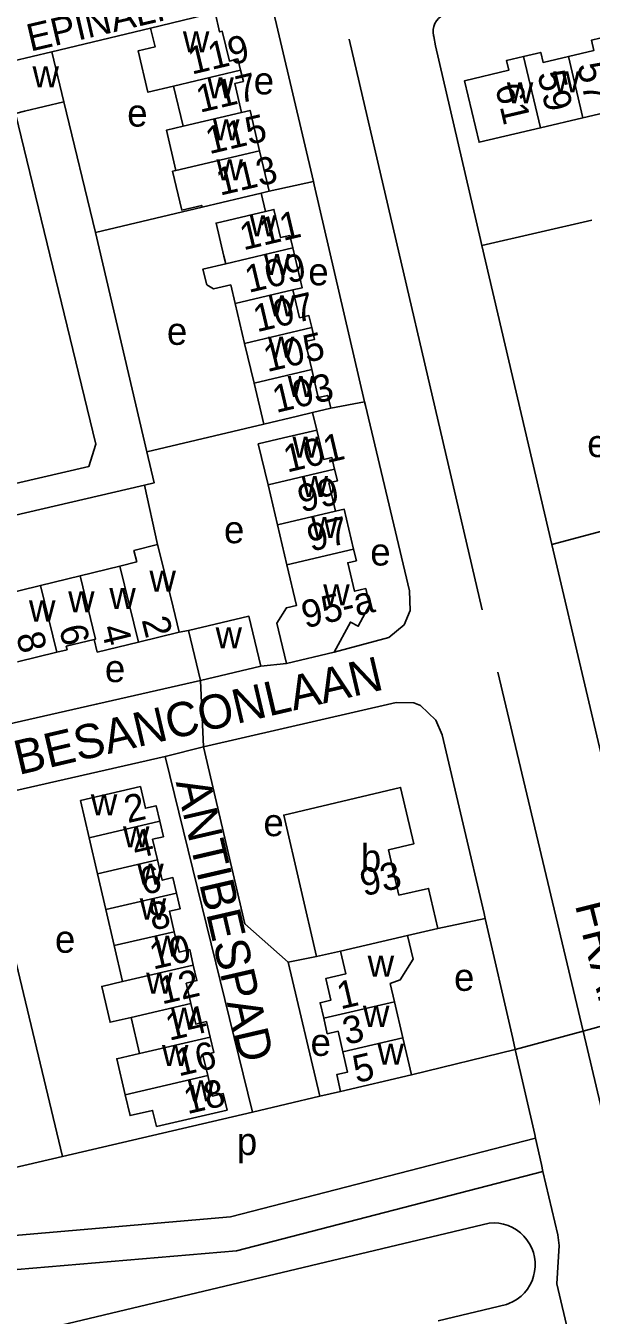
# Model space of a CAD drawing. Extents: x 157768 to 159790, y 387230 to 389604.
# Drawn here: x 159272.3 to 159355, y 388292.4 to 388480.9 of the extents above; entities that cross this region are included whole.
import ezdxf

# ---------------------------------------------------------------- set-up
doc = ezdxf.new("R2010")
doc.units = 0
for name, color, linetype in [('BLT_Basislijn', 7, 'Continuous'), ('BLT_Bebouwing', 7, 'Continuous'), ('BLT_Centroide', 7, 'Continuous'), ('BLT_Huisnummer', 7, 'Continuous'), ('BLT_Huisnummer_ tussenligend', 7, 'Continuous'), ('BLT_Huisnummer_reeks', 7, 'Continuous'), ('BLT_Onderverdeling_panden', 7, 'Continuous'), ('BLT_Straatnaam', 7, 'Continuous'), ('BLT_Straatnaam_verkleind', 7, 'Continuous'), ('BLT_Vlakafsluiter', 7, 'Continuous')]:
    doc.layers.add(name, color=color, linetype=linetype)

msp = doc.modelspace()

# ---------------------------------------------------------------- linework, layer by layer
at = {"layer": 'BLT_Basislijn'}
for p, q in [((159314.37, 388458.12), (159308.15, 388484.57)), ((159276.16, 388477.1), (159290.58, 388480.53)), ((159319.59, 388478.93), (159339.01, 388395.52)), ((159332.23, 388477.95), (159331.97, 388479.3)), ((159282.52, 388450.68), (159277.89, 388469.76)), ((159307.9, 388456.71), (159314.37, 388458.12)), ((159306.74, 388456.43), (159307.36, 388453.76)), ((159298.12, 388454.39), (159282.52, 388450.68)), ((159355.07, 388452.48), (159338.98, 388448.78)), ((159290.03, 388418.62), (159282.52, 388450.68)), ((159349.2, 388405.07), (159338.98, 388448.78)), ((159316.91, 388424.97), (159321.83, 388425.93)), ((159314.25, 388424.34), (159314.87, 388421.8)), ((159307.11, 388422.65), (159290.03, 388418.62)), ((159289.69, 388413.74), (159254.44, 388405.52)), ((159289.69, 388413.74), (159291.61, 388405.06)), ((159365.34, 388409.41), (159349.2, 388405.07)), ((159364.02, 388341.94), (159349.2, 388405.07)), ((159294.75, 388392.26), (159296.13, 388392.5)), ((159310.43, 388387.68), (159306.68, 388387.3)), ((159298.32, 388375.48), (159292.72, 388374.1)), ((159292.72, 388374.1), (159265.24, 388367.85)), ((159292.72, 388374.1), (159305.46, 388322.11)), ((159332.56, 388348.95), (159339.49, 388350.38)), ((159310.66, 388344.01), (159314.82, 388344.82)), ((159315.32, 388324.42), (159310.66, 388344.01)), ((159343.86, 388331.23), (159328.7, 388327.55)), ((159346.72, 388318.8), (159343.86, 388331.23)), ((159315.32, 388324.42), (159318.35, 388325.13)), ((159277.7, 388315.6), (159305.46, 388322.11)), ((159346.72, 388318.8), (159346.83, 388318.3)), ((159346.83, 388318.3), (159347.68, 388314.45)), ((159347.92, 388313.42), (159347.68, 388314.45)), ((159340.07, 388305.87), (159246.76, 388283.66)), ((159342.61, 388293.98), (159332.6, 388291.59))]:
    msp.add_line(p, q, dxfattribs=at)
for points in [[(159333.85, 388482.59), (159333.41, 388482.44), (159333.01, 388482.23), (159332.66, 388481.95), (159332.36, 388481.61), (159332.12, 388481.22), (159331.95, 388480.8), (159331.87, 388480.36), (159331.86, 388479.9), (159331.93, 388479.45), (159331.97, 388479.3)], [(159338.98, 388448.78), (159338.78, 388449.66), (159332.23, 388477.95)], [(159272.14, 388468.4), (159270.83, 388468.08), (159282.56, 388419.71), (159281.56, 388416.49), (159270.83, 388413.99)], [(159321.83, 388425.93), (159314.49, 388457.63), (159314.37, 388458.12)], [(159321.83, 388425.93), (159321.96, 388425.36), (159328.4, 388398.28), (159328.53, 388395.41), (159327.63, 388393.3), (159325.4, 388391.49), (159317.39, 388389.33)], [(159290.03, 388418.62), (159291.08, 388414.06), (159289.69, 388413.74)], [(159254.44, 388405.52), (159260.14, 388382.59), (159262.58, 388379.56), (159264.32, 388378.64), (159267.37, 388378.29), (159297.85, 388385.21)], [(159353.77, 388333.95), (159341.32, 388386.38)], [(159298.32, 388375.48), (159326.45, 388381.96), (159329.06, 388381.94), (159330, 388381.51), (159332.24, 388379.41), (159333.2, 388377.25), (159339.32, 388351.11), (159339.49, 388350.38)], [(159298.32, 388375.48), (159304.35, 388349.6), (159310.66, 388344.01)], [(159277.7, 388315.6), (159269.35, 388350.66), (159261.4, 388354.78)], [(159343.86, 388331.23), (159343.49, 388332.85), (159339.49, 388350.38)], [(159368.68, 388272.92), (159356.32, 388323.22), (159353.77, 388333.95)], [(159305.46, 388322.11), (159315.32, 388324.42)], [(159243.21, 388299.05), (159261.1, 388303.25), (159302.27, 388306.79), (159346.83, 388318.3)], [(159270.57, 388313.95), (159277.7, 388315.6)], [(159244.36, 388294.18), (159261.89, 388298.3), (159303.12, 388301.84), (159347.92, 388313.42)], [(159351.76, 388289.35), (159349.92, 388297), (159350.27, 388302.61), (159350.08, 388304.17), (159347.92, 388313.42)], [(159340.07, 388305.87), (159340.77, 388305.9), (159341.46, 388305.85), (159342.15, 388305.72), (159342.82, 388305.51), (159343.46, 388305.22), (159344.06, 388304.87), (159344.62, 388304.45), (159345.12, 388303.97), (159345.57, 388303.43), (159345.96, 388302.85), (159346.27, 388302.22), (159346.51, 388301.57), (159346.68, 388300.89), (159346.77, 388300.19), (159346.77, 388299.49), (159346.7, 388298.8), (159346.55, 388298.11), (159346.32, 388297.45), (159346.02, 388296.82), (159345.65, 388296.23), (159345.21, 388295.68), (159344.71, 388295.19), (159344.16, 388294.76), (159343.57, 388294.39), (159342.93, 388294.1), (159342.61, 388293.98)]]:
    msp.add_lwpolyline(points, dxfattribs=at)
at = {"layer": 'BLT_Bebouwing'}
for p, q in [((159270.4, 388475.74), (159276.16, 388477.1)), ((159276.16, 388477.1), (159277.89, 388469.76)), ((159295.32, 388466.2), (159293.94, 388472.06)), ((159277.89, 388469.76), (159272.14, 388468.4)), ((159353.76, 388467.43), (159347.54, 388465.97)), ((159298.12, 388454.39), (159306.74, 388456.43)), ((159306.74, 388456.43), (159307.9, 388456.71)), ((159302.94, 388440.27), (159304.31, 388434.47)), ((159305.69, 388428.64), (159307.11, 388422.65)), ((159314.25, 388424.34), (159316.91, 388424.97)), ((159309.12, 388407.92), (159307.74, 388413.77)), ((159310.5, 388402.09), (159309.12, 388407.92)), ((159280.29, 388400.5), (159286.07, 388401.92)), ((159268.73, 388397.66), (159274.51, 388399.08)), ((159294.75, 388392.26), (159288.79, 388390.8)), ((159297.85, 388385.21), (159296.13, 388392.5)), ((159317.39, 388389.33), (159310.43, 388387.68)), ((159306.68, 388387.3), (159297.85, 388385.21)), ((159282.81, 388356.95), (159281.59, 388362.21)), ((159284.04, 388351.69), (159282.81, 388356.95)), ((159285.26, 388346.43), (159284.04, 388351.69)), ((159332.56, 388348.95), (159328.13, 388347.92)), ((159286.49, 388341.17), (159285.26, 388346.43)), ((159318.32, 388345.63), (159314.82, 388344.82)), ((159326.21, 388338.21), (159327.44, 388332.95)), ((159288.94, 388330.65), (159287.72, 388335.91)), ((159327.44, 388332.95), (159328.7, 388327.55)), ((159328.7, 388327.55), (159318.35, 388325.13))]:
    msp.add_line(p, q, dxfattribs=at)
for points in [[(159300, 388482.81), (159290.58, 388480.53)], [(159303.74, 388474.38), (159303.35, 388476.04), (159302.09, 388475.74), (159301.06, 388480.08), (159300.67, 388479.99), (159300, 388482.81)], [(159290.58, 388480.53), (159291.23, 388477.8), (159288.75, 388477.21), (159290.18, 388471.18), (159293.94, 388472.06)], [(159351.65, 388476.41), (159355.36, 388477.28), (159355, 388478.78), (159357.45, 388479.35)], [(159347.54, 388465.97), (159338.57, 388463.86), (159336.45, 388472.86), (159342.91, 388474.38), (159342.57, 388475.8), (159345.09, 388476.39)], [(159345.09, 388476.39), (159347.6, 388476.99), (159347.94, 388475.54), (159351.65, 388476.41)], [(159303.86, 388468.22), (159302.87, 388472.43), (159304.13, 388472.72), (159303.74, 388474.38)], [(159359.76, 388468.85), (159353.76, 388467.43)], [(159306.5, 388462.63), (159305.11, 388468.52), (159303.86, 388468.22)], [(159294.28, 388459.74), (159292.89, 388465.63), (159295.32, 388466.2)], [(159307.9, 388456.71), (159306.5, 388462.63)], [(159298.12, 388454.39), (159298.06, 388454.64), (159295.14, 388453.95), (159293.8, 388459.62), (159294.28, 388459.74)], [(159307.36, 388453.76), (159300.15, 388452.05), (159301.3, 388447.19), (159301.56, 388446.11)], [(159311.36, 388448.43), (159310.93, 388450.24), (159309.58, 388449.92), (159308.61, 388454.05), (159307.36, 388453.76)], [(159311.38, 388442.27), (159312.74, 388442.59), (159311.36, 388448.43)], [(159301.56, 388446.11), (159298.23, 388445.32), (159298.81, 388443.04), (159299.75, 388442.42), (159302.29, 388443.02), (159302.94, 388440.27)], [(159314.12, 388436.78), (159313.71, 388438.52), (159312.35, 388438.2), (159311.38, 388442.27)], [(159314.12, 388430.63), (159313.15, 388434.72), (159314.53, 388435.05), (159314.12, 388436.78)], [(159304.31, 388434.47), (159305.69, 388428.64)], [(159316.91, 388424.97), (159316.46, 388426.86), (159315.08, 388426.53), (159314.12, 388430.63)], [(159307.11, 388422.65), (159312.05, 388423.82), (159314.25, 388424.34)], [(159307.74, 388413.77), (159306.32, 388419.77), (159310, 388420.65), (159314.87, 388421.8)], [(159314.87, 388421.8), (159315.88, 388417.5), (159317.07, 388417.78), (159317.47, 388416.07)], [(159317.47, 388416.07), (159317.88, 388414.36), (159316.63, 388414.06), (159317.61, 388409.93)], [(159317.61, 388409.93), (159318.87, 388410.22), (159320.25, 388404.39)], [(159286.07, 388401.92), (159288.56, 388402.53), (159288.14, 388404.21), (159291.61, 388405.06)], [(159291.61, 388405.06), (159293.56, 388397.12), (159294.75, 388392.26)], [(159320.25, 388404.39), (159320.65, 388402.7), (159319.39, 388402.4), (159320.38, 388398.24), (159322.02, 388398.63), (159322.59, 388396.21), (159320.92, 388393.11), (159319.77, 388393.73), (159317.39, 388389.33)], [(159310.43, 388387.68), (159309.28, 388392.55), (159309.04, 388393.56), (159310.43, 388395.81), (159311.9, 388396.16), (159310.5, 388402.09)], [(159274.51, 388399.08), (159280.29, 388400.5)], [(159296.13, 388392.5), (159304.95, 388394.59), (159306.68, 388387.3)], [(159282.33, 388391.2), (159278.26, 388390.2), (159278.38, 388389.68), (159276.9, 388389.32)], [(159288.79, 388390.8), (159282.79, 388389.33), (159282.33, 388391.2)], [(159276.9, 388389.32), (159271.12, 388387.92)], [(159280.32, 388367.65), (159289.09, 388369.69), (159289.83, 388366.52), (159291.39, 388366.89), (159291.92, 388364.62)], [(159314.82, 388344.82), (159310.03, 388365.52), (159327.12, 388369.55), (159329.04, 388361.3), (159325.32, 388360.43), (159326.86, 388353.81), (159331.19, 388354.8), (159332.56, 388348.95)], [(159281.59, 388362.21), (159280.32, 388367.65)], [(159291.92, 388364.62), (159292.45, 388362.35), (159290.88, 388361.98), (159291.58, 388358.99)], [(159291.58, 388358.99), (159292.28, 388356), (159293.84, 388356.37), (159294.37, 388354.1)], [(159294.37, 388354.1), (159294.9, 388351.83), (159293.33, 388351.46), (159294.03, 388348.47)], [(159294.03, 388348.47), (159294.73, 388345.48), (159296.29, 388345.85), (159296.82, 388343.58)], [(159328.13, 388347.92), (159328.94, 388344.45), (159327.07, 388341.44), (159325.59, 388340.89), (159326.21, 388338.21)], [(159315.87, 388335.82), (159315.35, 388338.09), (159316.91, 388338.45), (159316.18, 388341.61), (159319.09, 388342.29), (159318.32, 388345.63)], [(159296.82, 388343.58), (159297.35, 388341.31), (159295.78, 388340.94), (159296.48, 388337.95)], [(159287.72, 388335.91), (159284.67, 388335.22), (159283.45, 388340.48), (159286.49, 388341.17)], [(159296.48, 388337.95), (159297.17, 388334.96), (159298.74, 388335.33), (159299.27, 388333.06)], [(159318.66, 388330.92), (159317.97, 388333.91), (159316.4, 388333.55), (159315.87, 388335.82)], [(159299.27, 388333.06), (159299.8, 388330.79), (159298.23, 388330.42), (159298.93, 388327.43)], [(159286.86, 388324.64), (159285.64, 388329.9), (159288.94, 388330.65)], [(159318.35, 388325.13), (159317.78, 388327.57), (159319.35, 388327.93), (159318.66, 388330.92)], [(159298.93, 388327.43), (159299.62, 388324.44), (159301.19, 388324.81), (159301.76, 388322.37)], [(159291.43, 388319.97), (159290.88, 388322.34), (159287.57, 388321.58), (159286.86, 388324.64)], [(159301.76, 388322.37), (159291.43, 388319.97)]]:
    msp.add_lwpolyline(points, dxfattribs=at)
at = {"layer": 'BLT_Onderverdeling_panden'}
for p, q in [((159345.09, 388476.39), (159347.54, 388465.97)), ((159351.65, 388476.41), (159353.76, 388467.43)), ((159303.74, 388474.38), (159293.94, 388472.06)), ((159303.86, 388468.22), (159295.32, 388466.2)), ((159306.5, 388462.63), (159294.28, 388459.74)), ((159311.36, 388448.43), (159301.56, 388446.11)), ((159314.12, 388436.78), (159304.31, 388434.47)), ((159314.12, 388430.63), (159305.69, 388428.64)), ((159317.47, 388416.07), (159307.74, 388413.77)), ((159317.61, 388409.93), (159309.12, 388407.92)), ((159320.25, 388404.39), (159310.5, 388402.09)), ((159286.07, 388401.92), (159288.79, 388390.8)), ((159276.9, 388389.32), (159274.51, 388399.08)), ((159291.92, 388364.62), (159281.59, 388362.21)), ((159291.58, 388358.99), (159282.81, 388356.95)), ((159294.37, 388354.1), (159284.04, 388351.69)), ((159294.03, 388348.47), (159285.26, 388346.43)), ((159328.13, 388347.92), (159318.32, 388345.63)), ((159296.82, 388343.58), (159286.49, 388341.17)), ((159296.48, 388337.95), (159287.72, 388335.91)), ((159315.87, 388335.82), (159326.21, 388338.21)), ((159299.27, 388333.06), (159288.94, 388330.65)), ((159318.66, 388330.92), (159327.44, 388332.95)), ((159298.93, 388327.43), (159286.86, 388324.64))]:
    msp.add_line(p, q, dxfattribs=at)
for points in [[(159311.38, 388442.27), (159302.94, 388440.27)], [(159282.33, 388391.2), (159282.55, 388391.25), (159280.29, 388400.5)]]:
    msp.add_lwpolyline(points, dxfattribs=at)
at = {"layer": 'BLT_Vlakafsluiter'}
for p, q in [((159298.32, 388375.48), (159297.85, 388385.21)), ((159353.77, 388333.95), (159365.16, 388337.07)), ((159343.86, 388331.23), (159353.77, 388333.95))]:
    msp.add_line(p, q, dxfattribs=at)

# ---------------------------------------------------------------- texts
at = {"layer": 'BLT_Centroide'}
for s, p in [('w', (159295.3, 388477)), ('w', (159273.32, 388471.89)), ('w', (159298.87, 388470.28)), ('e', (159305.65, 388470.86)), ('w', (159342.64, 388469.56)), ('w', (159349.42, 388471.14)), ('e', (159287.16, 388466.15)), ('w', (159299.7, 388464.12)), ('w', (159300.2, 388458.28)), ('w', (159305.07, 388450.12)), ('w', (159307.12, 388444.47)), ('e', (159313.62, 388442.95)), ('w', (159307.84, 388438.41)), ('e', (159292.96, 388434.25)), ('w', (159307.72, 388432.38)), ('w', (159310.61, 388426.62)), ('w', (159311.3, 388417.78)), ('e', (159354.38, 388417.84)), ('w', (159312.64, 388412)), ('w', (159314.06, 388406)), ('e', (159301.3, 388405.25)), ('e', (159322.68, 388401.99)), ('w', (159290.41, 388398.16)), ('w', (159315.81, 388396.16)), ('w', (159278.53, 388395.17)), ('w', (159284.55, 388395.64)), ('w', (159272.81, 388393.81)), ('w', (159300.07, 388389.91)), ('e', (159283.9, 388384.95)), ('w', (159281.84, 388365.47)), ('e', (159307.07, 388362.43)), ('w', (159286.54, 388360.78)), ('b', (159321.3, 388357.25)), ('w', (159288.63, 388355.34)), ('w', (159288.99, 388350.25)), ('e', (159276.6, 388345.39)), ('w', (159291.09, 388344.81)), ('w', (159322.3, 388341.88)), ('w', (159289.92, 388339.41)), ('e', (159334.92, 388339.82)), ('w', (159293.54, 388334.31)), ('w', (159321.61, 388334.56)), ('e', (159313.95, 388330.31)), ('w', (159292.24, 388328.84)), ('w', (159323.73, 388329.03)), ('w', (159296.01, 388323.69)), ('p', (159303.18, 388315.82))]:
    msp.add_text(s, height=4, dxfattribs=at).set_placement(p)
at = {"layer": 'BLT_Huisnummer'}
for s, rotation, p in [('119', 13.3086, (159296.59, 388473.74)), ('57', 283.2284, (159352.86, 388475.12)), ('61', 283.2284, (159340.9, 388472)), ('113', 13.3086, (159300.71, 388456.04)), ('111', 13.3086, (159304.14, 388448.05)), ('107', 13.3086, (159306.11, 388436.08)), ('103', 13.3086, (159308.92, 388424.28)), ('101', 13.3086, (159310.53, 388415.57)), ('97', 13.3093, (159313.99, 388404)), ('6', 283.7803, (159277.17, 388392.88)), ('2', 283.779, (159289.25, 388394.06)), ('2', 13.1101, (159287.24, 388364.32)), ('6', 13.1101, (159289.57, 388353.8)), ('93', 13.1175, (159321.72, 388353.62)), ('10', 13.1101, (159290.95, 388342.91)), ('1', 13.0399, (159318.32, 388337.1)), ('14', 13.1101, (159293.29, 388332.51)), ('5', 13.1674, (159320.65, 388326.32)), ('18', 13.1101, (159295.95, 388321.78))]:
    msp.add_text(s, height=4, rotation=rotation, dxfattribs=at).set_placement(p)
at = {"layer": 'BLT_Huisnummer_ tussenligend'}
for s, rotation, p in [('59', 283.2284, (159347.07, 388473.88)), ('117', 13.3086, (159297.77, 388468.16)), ('115', 13.3086, (159299.15, 388462.1)), ('109', 13.3086, (159304.9, 388441.83)), ('105', 13.3086, (159307.61, 388430.25)), ('99', 13.3093, (159312.62, 388409.73)), ('8', 283.7803, (159270.91, 388391.81)), ('4', 283.779, (159283.3, 388392.9)), ('4', 13.1101, (159288.4, 388359.11)), ('8', 13.1101, (159290.85, 388348.6)), ('12', 13.1101, (159292.24, 388337.82)), ('3', 13.0399, (159319.15, 388331.91)), ('16', 13.1101, (159294.67, 388327.3))]:
    msp.add_text(s, height=4, rotation=rotation, dxfattribs=at).set_placement(p)
at = {"layer": 'BLT_Huisnummer_reeks'}
msp.add_text('95-a', height=4, rotation=13.308, dxfattribs=at).set_placement((159313.17, 388392.79))
at = {"layer": 'BLT_Straatnaam'}
for s, rotation, p in [('BESANCONLAAN', 13.1868, (159271.3, 388371.36)), ('ANTIBESPAD', 283.0263, (159294.24, 388370.33)), ('FRANSEBAAN', 284.1041, (159352.56, 388352.4))]:
    msp.add_text(s, height=5, rotation=rotation, dxfattribs=at).set_placement(p)
at = {"layer": 'BLT_Straatnaam_verkleind'}
msp.add_text('EPINALPAD', height=4, rotation=13.1215, dxfattribs=at).set_placement((159273.02, 388477.1))

doc.saveas('drawing.dxf')
